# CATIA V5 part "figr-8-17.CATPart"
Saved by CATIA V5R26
Part number: Part1
Bounding box of the stored display mesh (mm): x -55.501 to 55.501, y -84.223 to 84.223, z 0 to 81
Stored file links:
  D:\_Deepak\CATIA\CATIA V5-6R2016_Deepak\Resources\Part files\Partfiles\c08_catia_v5_6r2016_prt\figr-8-17.CATPart
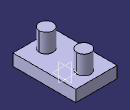
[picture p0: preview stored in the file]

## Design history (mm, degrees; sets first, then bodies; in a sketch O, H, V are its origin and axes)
Body1 (main body)
  Sketch1 on xy-plane, origin (0, 0, 0), H (1, 0, 0), V (0, 1, 0)
    line L1 (-55.501, 84.2232) -> (55.501, 84.2232)
    line L2 (55.501, 84.2232) -> (55.501, -84.2232)
    line L3 (55.501, -84.2232) -> (-55.501, -84.2232)
    line L4 (-55.501, -84.2232) -> (-55.501, 84.2232)
    axis line L5 (55.501, -84.2232) -> (-55.501, 84.2232)
    horizontal: L1 H, L3 H
    vertical: L2 V, L4 V
    midpoint: O L5
  Pad1: profile Sketch1, direction (0, 0, 1), length 31
  Sketch2 on face of Pad1, origin (0, 0, 31), H (1, 0, 0), V (0, 1, 0)
    circle A1 centre (0, -50.4568) radius 18.9426
    point P1 (0, -50.4568)
    coincidence: P1 V
  Pad2: profile Sketch2, direction (0, 0, 1), length 50
  Mirror1: of Pad2, Sketch2, about zx-plane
